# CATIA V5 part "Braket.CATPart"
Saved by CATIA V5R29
Part number: Braket
Source: Unknown
Bounding box of the stored display mesh (mm): x -60 to 0, y -30 to 30, z 0 to 60
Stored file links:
  C:\가치같이\SmartFactory_BoxErectorConveyor\Boxing(over)\Braket.CATPart
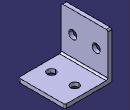
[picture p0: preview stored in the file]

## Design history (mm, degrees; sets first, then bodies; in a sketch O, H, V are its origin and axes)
Body1 (main body)
  Solid1 "PartBody": solid without history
